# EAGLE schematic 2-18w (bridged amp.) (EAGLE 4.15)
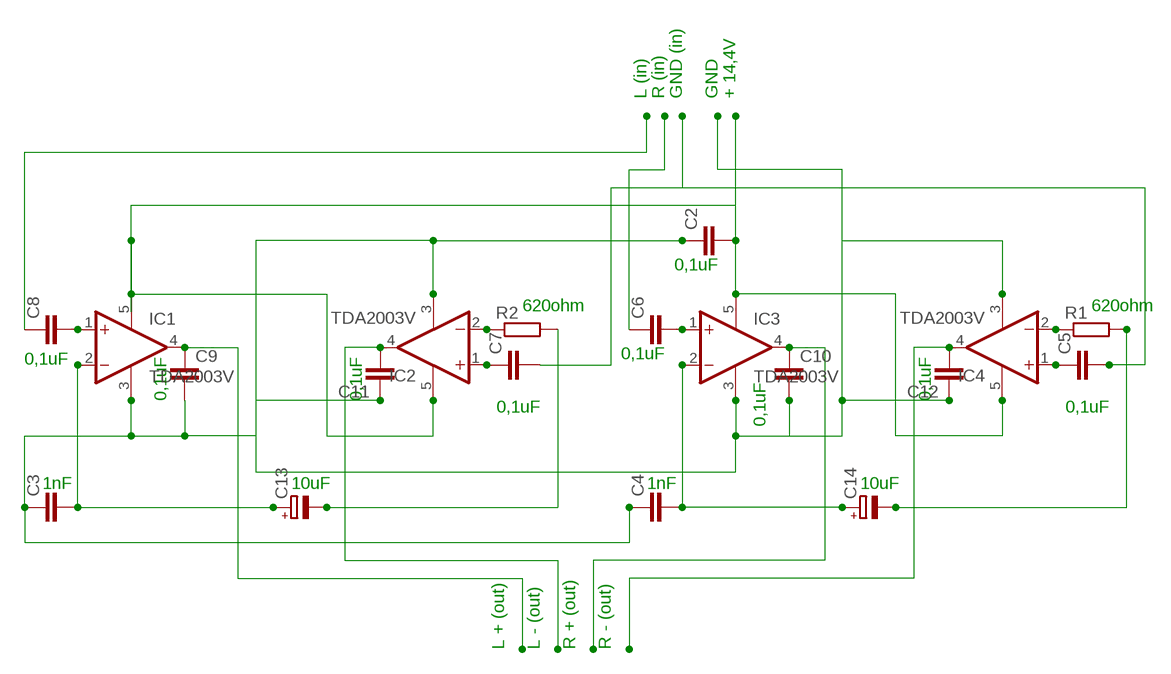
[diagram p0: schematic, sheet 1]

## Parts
C2  C-EU050-024X044  [C050-024X044]
C3  C-EU050-024X044  [C050-024X044]
C4  C-EU050-024X044  [C050-024X044]
C5  C-EU050-024X044  [C050-024X044]
C6  C-EU050-024X044  [C050-024X044]
C7  C-EU050-024X044  [C050-024X044]
C8  C-EU050-024X044  [C050-024X044]
C9  C-EU050-024X044  [C050-024X044]
C10  C-EU050-024X044  [C050-024X044]
C11  C-EU050-024X044  [C050-024X044]
C12  C-EU050-024X044  [C050-024X044]
C13  CPOL-EUE2.5-6  [E2,5-6]
C14  CPOL-EUE2.5-6  [E2,5-6]
IC1  TDA2003V  [CB360]
IC2  TDA2003V  [CB360]
IC3  TDA2003V  [CB360]
IC4  TDA2003V  [CB360]
R1  R-EU_0207/7  [0207/7]
R2  R-EU_0207/7  [0207/7]

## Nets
N$1: C5.1 IC4.1(+IN)
N$2: C6.2 IC3.1(+IN)
N$3: C7.1 IC2.1(+IN)
N$4: C8.2 IC1.1(+IN)
N$5: C9.1 IC1.4(OUT)
N$6: C10.1 IC3.4(OUT)
N$7: C11.2 IC2.4(OUT)
N$8: C12.2 IC4.4(OUT)
N$9: IC4.2(-IN) R1.1
N$10: IC2.2(-IN) R2.1
N$12: C13.- R2.2
N$13: C3.2 C13.+ IC1.2(-IN)
N$14: C2.1 C3.1 C4.1 C9.2 C10.2 C11.1 C12.1 IC1.3(GND) IC2.3(GND) IC3.3(GND) IC4.3(GND)
N$15: C4.2 C14.+ IC3.2(-IN)
N$16: C8.1
N$17: C14.- R1.2
N$18: C2.2 IC1.5(V+) IC2.5(V+) IC3.5(V+) IC4.5(V+)
N$19: C6.1
N$20: C5.2 C7.2

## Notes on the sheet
- L (in) | R (in) | GND (in) | GND | + 14,4V
- 0,1uF
- 620ohm | 620ohm
- 0,1uF
- 0,1uF
- 0,1uF
- 0,1uF | 0,1uF | 0,1uF | 0,1uF | 0,1uF
- 1nF | 10uF | 1nF | 10uF
- L + (out) | L - (out) | R + (out) | R - (out)

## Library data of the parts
C2-C12 = rcl:C-EU: CAPACITOR, European symbol
C13 C14 = rcl:CPOL-EU: POLARIZED CAPACITOR, European symbol
IC1-IC4 = linear:TDA2003: AUDIO AMPLIFIER
R1 R2 = rcl:R-EU_: RESISTOR, European symbol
